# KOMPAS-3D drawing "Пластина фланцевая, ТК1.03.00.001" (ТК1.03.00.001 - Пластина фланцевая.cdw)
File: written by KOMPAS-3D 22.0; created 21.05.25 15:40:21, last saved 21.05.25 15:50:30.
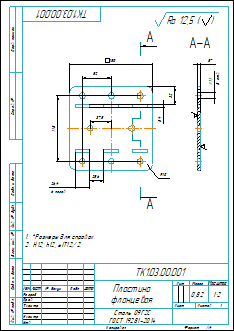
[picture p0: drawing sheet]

Sheet 1: A4, portrait

Document properties: Автор: TC; Знак неуказанной шероховатости: 4; Параметр неуказанной шероховатости: Ra 12,5; Масса: 0.815547

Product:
- Part/product: Пластина фланцевая  | designation ТК1.03.00.001
    Масса: 0.815547
    Форматы листов документа: A4

Title block, sheet 1: Наименование: Пластина / фланцевая; designation: ТК1.03.00.001; Материал: Сталь 09Г2С / ГОСТ 19281-2014; Масса: 0,82; Количество листов документа: 1; Форматы листов документа: A4; stored path: D:\Рабочая папка\АРХИВ\612\05\Задание №6 - Тележка для крыши\3Д\Узел монтажный\ТК1.03.00.001 - Пластина фланцевая.cdw

Views: Вид 1, Снизу, Разрез А-А
Referenced files in D:\Рабочая папка\АРХИВ\612\05\Задание №6 - Тележка для крыши\3Д\Узел монтажный\: Пластина фланцевая.m3d
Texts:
  Ra 12,5
  Ra 12,5 ( )
  BOSimple***Material:4ccf0190-16b6-4223-9222-aa108d28a442
  ТК1.03.00.001 Пластина фланцевая
Dimensions and other numbers on the sheet: 150; 118; 52; 37,5; 32; 5,4; 25,6; 26,4; 6 пазов; 10; 5; 11; 8 отв.; 1:2; 1; 0,82

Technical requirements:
  *Размеры для справок.
  H12, h12, ±IT12/2.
